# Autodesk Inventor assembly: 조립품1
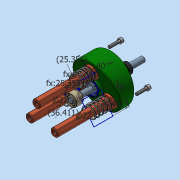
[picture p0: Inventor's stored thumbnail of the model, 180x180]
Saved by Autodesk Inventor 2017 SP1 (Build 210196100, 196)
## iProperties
Part Number: 조립품1
Material: 일반
Document SubType Name: Assembly
Designer: MRC
Author: MRC
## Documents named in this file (14)
- C:\Users\MRC\Desktop\610708V1011\조립품1.iam
- C:\Users\MRC\Desktop\610708V1011\본체.ipt
- C:\Users\MRC\Desktop\610708V1011\가변스프링1.ipt
- C:\Users\MRC\Desktop\610708V1011\가변스프링2.ipt
- C:\Users\MRC\Desktop\610708V1011\가변스프링3.ipt
- C:\Users\MRC\Desktop\610708V1011\멈춤링 10 x 1.ipt
- C:\Users\MRC\Desktop\610708V1011\멈춤링 22 x 1.2.ipt
- C:\Users\MRC\Desktop\610708V1011\메인 축.ipt
- C:\Users\MRC\Desktop\610708V1011\베어링 NA 4900.ipt
- C:\Users\MRC\Desktop\610708V1011\볼트 M5.ipt
- C:\Users\MRC\Desktop\610708V1011\슬라이드 축.ipt
- C:\Users\MRC\Desktop\610708V1011\오일실.ipt
- C:\Users\MRC\Desktop\610708V1011\커버.ipt
- C:\Users\MRC\Desktop\610708V1011\판캠.ipt
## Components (3 placed, 3 different names)
1. 가변스프링1:1
2. 가변스프링2:1
3. 가변스프링3:1
